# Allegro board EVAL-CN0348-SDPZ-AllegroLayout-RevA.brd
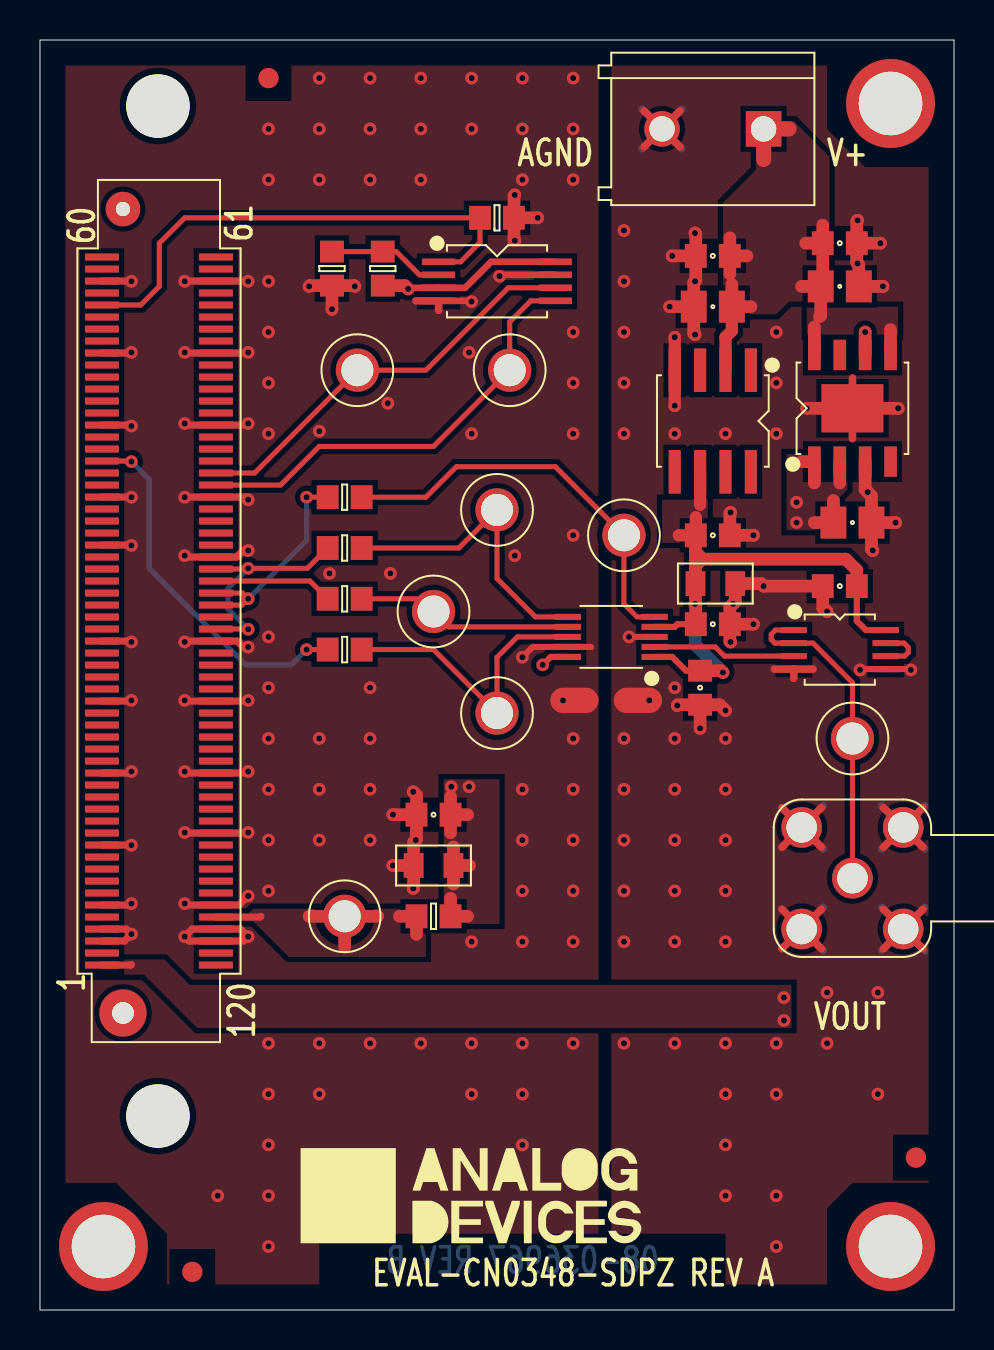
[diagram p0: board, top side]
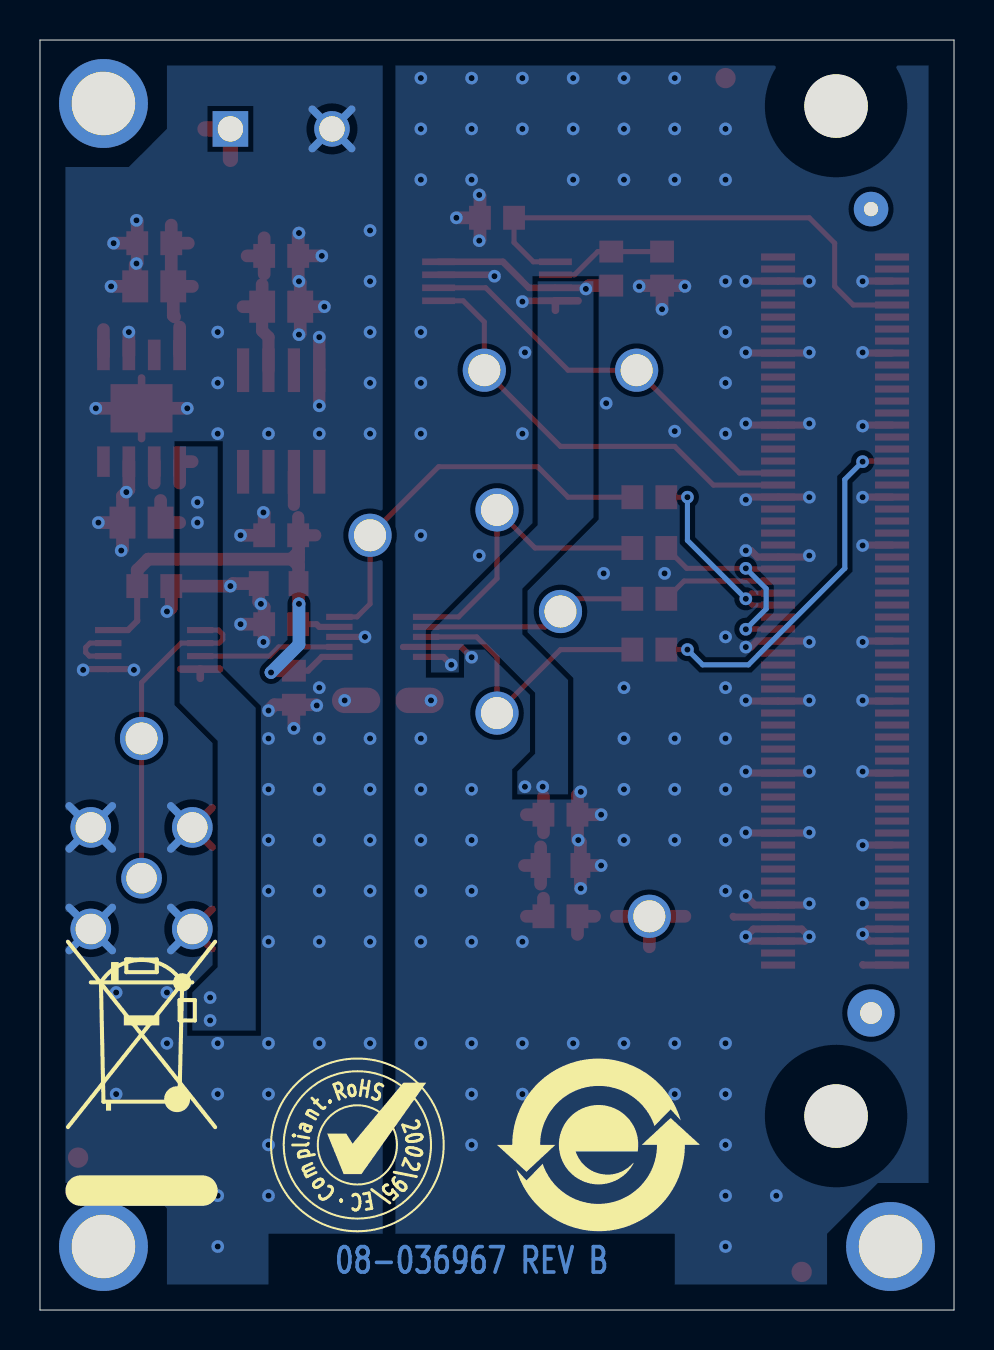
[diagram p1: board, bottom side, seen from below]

Outline 45.72 x 63.5 mm; copper layers: TOP, BOTTOM. Coordinates in mm from the lower left corner of the outline.
Outline path: 0,63.5 0,0 45.72,0 45.72,63.5 0,63.5

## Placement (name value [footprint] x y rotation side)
C1  0.1uF  [C0805]  40 51.18 0 top
C2  1UF  [C0603]  40 53.34 0 top
C3  1uF  [C0805]  40.64 39.37 0 top
C4  0.1uF  [C0805]  33.66 50.16 180 top
C5  1UF  [C0603]  33.66 52.7 180 top
C6  0.1uF  [C0603]  33.66 38.73 0 top
C7  0.1uF  [C0603]  33.66 34.29 180 top
C8  10uF  [C0805-2]  33.78 36.32 180 top
C9  0.1uF  [C0603]  33.02 31.11 270 top
C10  0.1uF  [C0603]  40 36.2 0 top
C12  10uF  [C0805-2]  19.69 22.23 180 top
C13  0.1uF  [C0603]  19.69 24.77 180 top
CS  BLK  [CNLOOPTP]  29.21 38.73 0 top
DIN  BLK  [CNLOOPTP]  19.69 34.92 0 top
J1  KRM2 02  [CNTERM_2P]  36.2 59.05 180 top
J2  FX8-120S-SV(21)  [CNHRSFX8-120S-SV_A]  5.95 34.95 90 top
J3  MACOM5164-5003-09  [CNMACOM5164-5003-09]  40.64 21.59 180 top
LDAC  BLK  [CNLOOPTP]  22.86 29.84 0 top
NOREF  -  []  -47.88 212.47 0 top
NOREF#2  -  [unnamed#2]  3.17 3.17 0 top
NOREF#3  -  []  -184.15 -215.9 0 top
NOREF#4  -  []  28.57 90.81 0 top
NOREF#5  -  []  0 0 0 top
NOREF#6  -  []  0 0 0 top
NOREF#7  -  []  182.25 261.87 0 top
NOREF#8  -  []  21.59 5.71 0 top
NOREF#9  -  []  11.43 61.59 0 top
NOREF#10  -  []  0 63.5 0 top
NOREF#11  -  []  -125.48 255.91 0 top
NOREF#12  -  []  -182.88 -214.63 0 top
NOREF#13  -  []  45.72 0 90 top
NOREF#14  -  [unnamed#2]  7.62 1.91 0 top
NOREF#15  -  [unnamed#2]  43.81 7.62 0 top
NOREF#16  -  []  11.43 61.59 0 top
NOREF#17  -  [unnamed#2]  42.55 3.17 0 top
NOREF#18  -  []  11.43 61.59 0 top
NOREF#19  -  []  0 63.5 0 top
NOREF#20  -  []  45.72 0 90 top
NOREF#21  -  []  -175.26 -205.49 0 top
NOREF#22  -  [unnamed#2]  42.55 60.32 0 top
NOREF#23  -  []  0 0 0 top
NOREF#24  -  [unnamed#2]  11.43 61.59 0 top
NOREF#25  -  []  45.72 63.5 0 top
NOREF#26  -  []  45.72 63.5 180 top
NOREF#27  -  []  0 63.5 270 top
NOREF#28  -  []  17.78 8.25 180 bottom
NOREF#29  -  []  29.84 8.25 180 bottom
NOREF#30  -  []  31.37 22.1 180 bottom
R1  33  [R0603]  15.24 40.64 0 top
R2  33  [R0603]  15.24 35.56 0 top
R3  33  [R0603]  15.24 38.1 0 top
R4  33  [R0603]  15.24 33.02 0 top
R5  100K  [R0603]  22.86 54.61 0 top
R6  0  [R0603]  17.14 52.07 90 top
R7  100K  [R0603]  14.61 52.07 270 top
R8  0  [R0603]  19.69 19.69 0 top
SCL  BLK  [CNLOOPTP]  15.88 46.99 0 top
SCLK  BLK  [CNLOOPTP]  22.86 40 0 top
SDA  BLK  [CNLOOPTP]  23.49 46.99 0 top
SNS1  SNS  [NCSNS50MIL]  27.3 30.48 0 top
U1  ADP7104ARDZ-5.0  [SO8NB-PAD3_1X2_41]  40.64 45.08 0 top
U2  ADR4550BRZ  [SO8]  33.66 44.45 180 top
U3  AD5541ABRMZ  [RM10]  28.57 33.66 90 top
U4  ADA4500-2AMRZ  [MSOP8]  40 33.02 270 top
U5  24LC32A-I/ST  [TSSOP8]  22.86 51.44 270 top
UNK3.3V  BLK  [CNLOOPTP]  15.24 19.69 0 top
VOUT  BLK  [CNLOOPTP]  40.64 28.57 0 top

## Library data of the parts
C1 C4 = CAP: Tolerance: 10; User Part Number: UPN; alternate symbols: (C0402H22_ALT,C0201-2,C0402_A); part number: CAP_SM-0.1UF,25V,10,E012855,C0805; tolerance: 10
C2 C5 = CAP: Tolerance: 10; User Part Number: UPN; alternate symbols: (C0402H22_ALT,C0201-2,C0402_A); part number: CAP_SM-1UF,25V,10,E006992,C0603; tolerance: 10
C3 = CAP: Tolerance: 10; User Part Number: UPN; alternate symbols: (C0402H22_ALT,C0201-2,C0402_A); part number: CAP_SM-1UF,16V,10,E011046,C0805; tolerance: 10
C6 C7 C9 C10 C13 = CAP: Tolerance: 10; User Part Number: UPN; alternate symbols: (C0402H22_ALT,C0201-2,C0402_A); part number: CAP_SM-0.1UF,16V,10,E011547,C0603; tolerance: 10
C8 C12 = CAP: Tolerance: 10; User Part Number: UPN; alternate symbols: (C0402H22_ALT,C0201-2,C0402_A); part number: CAP_SM-10UF,10V,10,E013940,C0805-2; tolerance: 10
CS DIN LDAC SCL SCLK SDA UNK3.3V VOUT = CNTP1P: User Part Number: UPN; alternate symbols: (CNBANANA_ALT); part number: CNTP1P_TH-BLK,E000948,CNLOOPTP
J1 = CN2P: User Part Number: UPN; part number: CN2P_TH-KRM2 02,E000796,CNTERM_2P
J2 = CN120P_V4: User Part Number: UPN; part number: CN120P_V4_SM-FX8-120S-SV(21),E016993,CNHRSFX8-120S-SV_A
J3 = CNBNC5P: User Part Number: UPN; part number: CNBNC5P_TH-MACOM5164-5003-09,E000920,CNMACOM5164-5003-09
R1-R4 = RES: Tolerance: 1; User Part Number: UPN; alternate symbols: (RRAD984L1500W75H520LD32;TO220H590_ALT;R0402_A;R0603_A); part number: RES_SM-33,1/4W,1,E019276,R0603; tolerance: 1
R5 R7 = RES: Tolerance: 1; User Part Number: UPN; alternate symbols: (RRAD984L1500W75H520LD32;TO220H590_ALT;R0402_A;R0603_A); part number: RES_SM-100K,1/10W,1,E010279,R0603; tolerance: 1
R6 R8 = RES: Tolerance: 1; User Part Number: UPN; alternate symbols: (RRAD984L1500W75H520LD32;TO220H590_ALT;R0402_A;R0603_A); part number: RES_SM-0,1/16W,1,E004207,R0603; tolerance: 1
SNS1 = NCSENSE: User Part Number: UPN; part number: NCSENSE_SM-SNS,E005619,NCSNS50MIL
U1 = ADP7104: User Part Number: UPN; part number: ADP7104_SM-ADP7104ARDZ-5.0,E016720,SO8NB-PAD3_1X2_41,N/A
U2 = ADR45XX: User Part Number: UPN; part number: ADR45XX_SM-ADR4550BRZ,E016255,SO8,N/A
U3 = AD5541A: User Part Number: UPN; part number: AD5541A_SM-AD5541ABRMZ,E015582,RM10,N/A
U4 = ADA4500_2: User Part Number: UPN; part number: ADA4500_2_SM-ADA4500-2AMRZ,E017613,MSOP8,N/A
U5 = IC24FC256: User Part Number: UPN; part number: IC24FC256_SM-24LC32A-I/ST,E014553,TSSOP8

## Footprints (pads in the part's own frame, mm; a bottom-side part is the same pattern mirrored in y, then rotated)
C0603
  rect 1.092x1.194 smd: 1(-0.851,0) 2(0.851,0)
C0805
  rect 1.295x1.6 smd: 1(-0.953,0) 2(0.953,0)
C0805-2
  rect 0.991x1.245 smd: 1(-0.996,0) 2(0.996,0)
CNHRSFX8-120S-SV_A
  round 3.302 hole 3.175 unplated: (-25.25,0.051) (25.25,0.051)
  round 2.362 hole 1.092 unplated: (-20.099,1.801)
  round 1.727 hole 0.711 unplated: (20.099,1.801)
  rect 0.356x1.702 smd: 1(-17.701,2.85) 2(-17.099,2.85) 3(-16.5,2.85) 4(-15.9,2.85) 5(-15.301,2.85) 6(-14.699,2.85) 7(-14.1,2.85) 8(-13.5,2.85) 9(-12.901,2.85) 10(-12.301,2.85) 11(-11.699,2.85) 12(-11.1,2.85) 13(-10.5,2.85) 14(-9.901,2.85) 15(-9.299,2.85) 16(-8.7,2.85) 17(-8.1,2.85) 18(-7.501,2.85) 19(-6.901,2.85) 20(-6.299,2.85) 21(-5.7,2.85) 22(-5.1,2.85) 23(-4.501,2.85) 24(-3.899,2.85) 25(-3.299,2.85) 26(-2.7,2.85) 27(-2.101,2.85) 28(-1.501,2.85) 29(-0.899,2.85) 30(-0.3,2.85) 31(0.3,2.85) 32(0.899,2.85) 33(1.501,2.85) 34(2.101,2.85) 35(2.7,2.85) 36(3.299,2.85) 37(3.899,2.85) 38(4.501,2.85) 39(5.1,2.85) 40(5.7,2.85) 41(6.299,2.85) 42(6.901,2.85) 43(7.501,2.85) 44(8.1,2.85) 45(8.7,2.85) 46(9.299,2.85) 47(9.901,2.85) 48(10.5,2.85) 49(11.1,2.85) 50(11.699,2.85) 51(12.301,2.85) 52(12.901,2.85) 53(13.5,2.85) 54(14.1,2.85) 55(14.699,2.85) 56(15.301,2.85) 57(15.9,2.85) 58(16.5,2.85) 59(17.099,2.85) 60(17.701,2.85) 61(17.701,-2.85) 62(17.099,-2.85) 63(16.5,-2.85) 64(15.9,-2.85) 65(15.301,-2.85) 66(14.699,-2.85) 67(14.1,-2.85) 68(13.5,-2.85) 69(12.901,-2.85) 70(12.301,-2.85) 71(11.699,-2.85) 72(11.1,-2.85) 73(10.5,-2.85) 74(9.901,-2.85) 75(9.299,-2.85) 76(8.7,-2.85) 77(8.1,-2.85) 78(7.501,-2.85) 79(6.901,-2.85) 80(6.299,-2.85) 81(5.7,-2.85) 82(5.1,-2.85) 83(4.501,-2.85) 84(3.899,-2.85) 85(3.299,-2.85) 86(2.7,-2.85) 87(2.101,-2.85) 88(1.501,-2.85) 89(0.899,-2.85) 90(0.3,-2.85) 91(-0.3,-2.85) 92(-0.899,-2.85) 93(-1.501,-2.85) 94(-2.101,-2.85) 95(-2.7,-2.85) 96(-3.299,-2.85) 97(-3.899,-2.85) 98(-4.501,-2.85) 99(-5.1,-2.85) 100(-5.7,-2.85) 101(-6.299,-2.85) 102(-6.901,-2.85) 103(-7.501,-2.85) 104(-8.1,-2.85) 105(-8.7,-2.85) 106(-9.299,-2.85) 107(-9.901,-2.85) 108(-10.5,-2.85) 109(-11.1,-2.85) 110(-11.699,-2.85) 111(-12.301,-2.85) 112(-12.901,-2.85) 113(-13.5,-2.85) 114(-14.1,-2.85) 115(-14.699,-2.85) 116(-15.301,-2.85) 117(-15.9,-2.85) 118(-16.5,-2.85) 119(-17.099,-2.85) 120(-17.701,-2.85)
CNLOOPTP
  round 2.159 hole 1.6: 1(0,0)
CNMACOM5164-5003-09
  round 2.032 hole 1.524: 1(0,0) 2(-2.54,2.54) 3(2.54,2.54) 4(2.54,-2.54) 5(-2.54,-2.54)
CNTERM_2P
  rect 1.778x1.778 hole 1.27: 1(0,0)
  round 1.778 hole 1.27: 2(5.08,0)
MSOP8
  rect 0.305x1.321 smd: 1(-0.975,-2.301) 2(-0.325,-2.301) 3(0.325,-2.301) 4(0.975,-2.301) 5(0.975,2.301) 6(0.325,2.301) 7(-0.325,2.301) 8(-0.975,2.301)
NCSNS50MIL
  round 0.127 smd: 1(0,0) 2(2.032,0)
R0603
  rect 1.092x1.194 smd: 1(-0.851,0) 2(0.851,0)
RM10
  rect 0.305x1.321 smd: 1(-1.001,-2.172) 2(-0.5,-2.172) 3(0,-2.172) 4(0.5,-2.172) 5(1.001,-2.172) 6(1.001,2.172) 7(0.5,2.172) 8(0,2.172) 9(-0.5,2.172) 10(-1.001,2.172)
SO8
  rect 0.61x2.184 smd: 1(-1.905,-2.54) 2(-0.635,-2.54) 3(0.635,-2.54) 4(1.905,-2.54) 5(1.905,2.54) 6(0.635,2.54) 7(-0.635,2.54) 8(-1.905,2.54)
SO8NB-PAD3_1X2_41
  rect 0.635x1.524 smd: 1(-1.905,-2.667) 2(-0.635,-2.667) 3(0.635,-2.667) 4(1.905,-2.667) 5(1.905,2.667) 6(0.635,2.667) 7(-0.635,2.667) 8(-1.905,2.667)
  rect 3.099x2.413 smd: PAD(0,0)
TSSOP8
  rect 0.33x1.651 smd: 1(-0.975,-2.921) 2(-0.325,-2.921) 3(0.325,-2.921) 4(0.975,-2.921) 5(0.975,2.921) 6(0.325,2.921) 7(-0.325,2.921) 8(-0.975,2.921)
unnamed#2
  round 4.445 hole 3.175 unplated: (0,0)

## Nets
3.3V: C12.1(N1) C13.1(N1) R6.1(N1) R8.2(N2) U3.10(VLOGIC) U5.3(A2) U5.8(VCC)
+5V: C6.1(N1) C7.2(N2) C8.2(N2) C9.1(N1) C10.2(N2) U2.6(VOUT) U3.1(VDD) U3.4(REF) U4.8(V+)
AGND: C1.2(N2) C2.2(N2) C3.2(N2) C4.2(N2) C5.2(N2) C6.2(N2) C7.1(N1) C8.1(N1) C9.2(N2) C10.1(N1) J1.2(N2) J3.2(SH1) J3.3(SH2) J3.4(SH3) J3.5(SH4) SNS1.2(N2) U1.3(GND1) U1.6(GND2) U1.PAD U2.4(GND) U3.3(AGND) U4.4(V-) U4.5(NINV)
DGND: C12.2(N2) C13.2(N2) J2.3(GND1) J2.4(GND2) J2.6(GND3) J2.11(GND4) J2.17(GND5) J2.23(GND6) J2.28(GND7) J2.36(GND8) J2.40(GND9) J2.46(GND10) J2.52(GND11) J2.58(GND12) J2.63(GND13) J2.69(GND14) J2.75(GND15) J2.81(GND16) J2.86(GND17) J2.93(GND18) J2.98(GND19) J2.104(GND20) J2.109(GND21) J2.115(GND22) J2.117(GND23) J2.118(GND24) R5.2(N2) R7.2(N2) SNS1.1(N1) U3.9(DGND) U5.4(VSS) U5.7(WP)
DAC_/LDAC: J2.43(GPIO0) R4.1(N1)
DAC_CS: J2.89(SPORT_TFS) J2.90(SPORT_RFS) R1.1(N1)
DAC_DIN: J2.88(SPORT_DT0) R2.1(N1)
DAC_SCLK: J2.87(SPORT_TSCLK) J2.92(SPORT_RSCLK) R3.1(N1)
SDP_+5V: C3.1(N1) J2.1(VIN) U1.1(VOUT) U1.2(SENSE)
UNNAMED_3_CN120PV4_I1_EEPROMA0: J2.56(EEPROM_A0) R5.1(N1) U5.1(A0)
UNNAMED_3_CN120PV4_I1_SCL0: J2.79(SCL_0) SCL.1(N1) U5.6(SCL)
UNNAMED_3_CN120PV4_I1_SDA0: J2.80(SDA_0) SDA.1(N1) U5.5(SDA)
UNNAMED_3_CN120PV4_I1_VIO: J2.116(VIO(+3.3V)) R8.1(N1) UNK3.3V.1
UNNAMED_3_IC24FC256_I4_A1: R6.2(N2) R7.1(N1) U5.2(A1)
UNNAMED_5_AD5541A_I1_CSN: CS.1(N1) R1.2(N2) U3.5(CS_N)
UNNAMED_5_AD5541A_I1_DIN: DIN.1(N1) R2.2(N2) U3.7(DIN)
UNNAMED_5_AD5541A_I1_LDACN: LDAC.1(N1) R4.2(N2) U3.8(LDAC_N)
UNNAMED_5_AD5541A_I1_SCLK: R3.2(N2) SCLK.1(N1) U3.6(SCLK)
UNNAMED_5_AD5541A_I1_VOUT: U3.2(VOUT) U4.3(NINV)
UNNAMED_5_ADA45002_I16_INV: U4.6(INV) U4.7(OUT)
VOUT: J3.1(CNTR) U4.1(OUT) U4.2(INV) VOUT.1(N1)
VPOS: C1.1(N1) C2.1(N1) C4.1(N1) C5.1(N1) J1.1(N1) U1.5(EN) U1.8(VIN) U2.2(VIN)

Pads without a net: J2 2 5 7 8 9 10 12 13 14 15 16 18 19 20 21 22 24 25 26 27 29 30 31 32 33 34 35 37 38 39 41 42 44 45 47 48 49 50 51 53 54 55 57 59 60 61 62 64 65 66 67 68 70 71 72 73 74 76 77 78 82 83 84 85 91 94 95 96 97 99 100 101 102 103 105 106 107 108 110 111 112 113 114 119 120; U1 4 7; U2 1 3 5 7 8

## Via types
v1: diameter 0.635, hole 0.305, TOP to BOTTOM, 208 vias

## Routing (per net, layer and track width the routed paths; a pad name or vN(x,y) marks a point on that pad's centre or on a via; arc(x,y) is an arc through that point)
3.3V: length 17.8
  TOP w0.305: v1(25.15,32.26) 25.54,32.65 U3.10
  TOP w0.33: U5.8 22.57,52.41 21.26,51.11 U5.3 18.47,51.11 v1(18.41,51.05)
  TOP w0.635: C13.1 20.54,25.67 ; C13.1 21.39,24.77 ; C13.1 20.54,23.86 ; C12.1 20.68,23.15 ; C12.1 21.48,22.23 ; C12.1 20.68,21.3 ; v1(18.41,51.05) 18.25,51.22 R6.1 ; 20.54,20.59 R8.2 21.39,19.69
  vias: v1(20.57,26.16) v1(21.46,26.16)
+5V: length 31.2
  TOP w0.305: U4.8 41.32,34 40.86,34.46 C10.2 ; U3.1 31.62,32.65 32.31,31.97 C9.1 ; C7.2 31.88,34.29 31.75,34.16 U3.4
  TOP w0.61: U2.6 33.02,40.26 ; 32.8,39.64 C6.1 31.95,38.73
  TOP w0.635: 32.79,37.9 32.79,38.72 C6.1 ; 32.79,37.9 33.15,37.54 ; 32.79,37.9 32.79,37.59 ; 32.79,37.21 C8.2 32.79,35.33 v1(32.77,35.31) 32.8,35.27 C7.2 ; 32.79,37.21 32.79,37.59 ; 32.79,37.21 33.12,37.54 ; 33.12,37.54 33.15,37.54 ; 33.12,37.54 32.84,37.54 32.79,37.59 ; 33.15,37.54 40.31,37.54 40.86,37 C10.2 ; C9.1 34.07,31.97 v1(34.16,31.88)
  BOTTOM w0.635: v1(34.16,31.88) 32.77,33.27 v1(32.77,35.31)
AGND: length 107.1
  TOP w0.305: v1(41.02,32) 41.06,32.04 U4.5 43.52,32.04 v1(43.56,32) ; U3.3 v1(29.46,33.66)
  TOP w0.381: SNS1.2 29.34,30.85 ; SNS1.2 29.34,30.11 ; SNS1.2 28.97,30.48 ; U4.4 38.67,32.04 ; U4.4 36.74,32.04 ; U4.4 37.7,31.58 ; 42.19,20.04 J3.2 ; J3.2 42.19,18.06 ; J3.2 44.17,20.04 ; J3.2 44.17,18.06 ; J3.4 39.09,25.12 ; J3.4 37.11,23.14 ; J3.4 37.11,25.12 ; J3.4 39.09,23.14 ; 30.22,58.16 31.11,59.05 ; 31.11,59.05 32.01,59.95 ; 31.11,59.05 32.01,58.16 ; 31.11,59.05 30.22,59.95 ; 40.64,43.57 U1.PAD 40.64,46.6 ; 37.11,20.04 J3.3 ; J3.3 39.09,18.06 ; J3.3 39.09,20.04 ; J3.3 37.11,18.06 ; J3.5 44.17,25.12 ; J3.5 42.19,23.14 ; J3.5 42.19,25.12 ; J3.5 44.17,23.14
  TOP w0.61: v1(31.75,48.64) U2.4 v1(31.75,45.21)
  TOP w0.635: v1(32.77,48.77) 32.7,48.83 C4.2 ; 41.27,47.75 v1(41.27,48.89) ; C9.2 31.92,30.26 v1(31.88,30.23) ; C9.2 34,30.26 v1(34.29,29.97) ; C9.2 v1(33.02,29.08) ; C4.2 v1(31.5,50.16) ; C4.2 32.7,51.37 v1(32.77,51.44) 32.8,51.47 C5.2 ; C7.1 34.51,33.44 v1(34.54,33.4) ; C7.1 34.51,35.14 v1(34.67,35.31) 34.78,35.41 C8.1 36.07,36.32 v1(36.2,36.2) C10.1 39.15,35.09 v1(39.37,34.92) ; C7.1 v1(35.69,34.29) ; v1(32.77,53.85) 32.8,53.81 C5.2 ; v1(41.66,37.97) 41.59,38.04 C3.2 ; C5.2 v1(31.62,52.7) ; v1(40.89,54.48) 40.86,54.44 C2.2 ; C3.2 v1(42.8,39.37) ; C3.2 41.59,40.7 v1(41.4,40.89) 41.27,41.02 41.27,42.42 ; v1(35.69,38.73) C6.2 34.51,39.84 v1(34.54,39.88) ; C2.2 v1(42.04,53.34) ; C2.2 40.86,52.36 v1(40.89,52.32) 40.96,52.26 C1.2 v1(42.16,51.18) ; v1(42.93,45.08) U1.PAD v1(38.35,45.08)
  TOP w1.27: SNS1.2 v1(30.48,30.48)
  BOTTOM w0.381: 42.1,23.05 J3.5 ; J3.5 44.26,23.05 ; J3.5 42.1,25.21 ; J3.5 44.26,25.21 ; 39.18,17.97 J3.3 39.18,20.13 ; 31.11,59.05 32.1,58.07 ; 31.11,59.05 30.13,60.04 ; 31.11,59.05 32.1,60.04 ; 31.11,59.05 30.13,58.07 ; J3.2 44.26,17.97 ; J3.2 42.1,20.13 ; J3.2 42.1,17.97 ; J3.2 44.26,20.13 ; 39.18,25.21 J3.4 39.18,23.05
  vias: v1(29.21,53.98) v1(29.21,51.44) v1(29.21,48.89) v1(29.21,46.35) v1(29.21,43.81) v1(29.21,28.57) v1(29.21,26.03) v1(29.21,23.49) v1(29.21,20.95) v1(29.21,18.41) v1(29.21,13.34) v1(31.75,43.81) v1(31.75,31.11) v1(31.75,28.57) v1(31.75,26.03) v1(31.75,23.49) v1(31.75,20.95) v1(31.75,18.41) v1(31.75,13.34) v1(34.29,43.81) v1(34.29,28.57) v1(34.29,26.03) v1(34.29,23.49) v1(34.29,20.95) v1(34.29,18.41) v1(34.29,13.34) v1(34.29,10.8) v1(34.29,8.25) v1(34.29,5.71) v1(36.83,48.89) v1(36.83,46.35) v1(36.83,43.81) v1(36.83,13.34) v1(36.83,10.8) v1(36.83,5.71) v1(36.83,3.17) v1(39.37,15.88) v1(39.37,13.34) v1(41.91,15.88) v1(41.91,10.8)
DGND: length 83.6
  TOP w0.305: 27.56,33.15 27.55,33.15 U3.9 24.65,33.15 v1(24.13,32.64)
  TOP w0.33: U5.4 21.55,50.46 v1(21.59,50.42) ; v1(22.99,51.69) 23.06,51.76 U5.7
  TOP w0.356: v1(4.57,47.88) 4.54,47.85 J2.52 ; v1(10.41,26.92) 10.34,26.85 J2.104 7.32,26.85 v1(7.24,26.92) ; v1(4.57,51.44) 4.56,51.45 J2.58 ; v1(4.57,44.2) 4.52,44.25 J2.46 ; J2.23 4.54,30.45 v1(4.57,30.48) ; v1(10.41,37.97) 10.16,37.97 9.83,37.65 J2.86 7.31,37.65 v1(7.24,37.72) ; J2.11 4.56,23.25 v1(4.57,23.24) ; J2.28 4.53,33.45 v1(4.57,33.4) ; v1(4.57,20.32) 4.5,20.25 J2.6 ; v1(7.24,40.64) 7.25,40.65 J2.81 10.28,40.65 v1(10.41,40.51) ; v1(7.24,30.48) 7.27,30.45 J2.98 10.38,30.45 v1(10.41,30.48) ; v1(10.41,44.32) 10.34,44.25 J2.75 7.32,44.25 v1(7.24,44.32) ; J2.17 4.5,26.85 v1(4.57,26.92) ; v1(7.24,23.88) 7.27,23.85 J2.109 10.39,23.85 v1(10.41,23.88) ; J2.40 4.56,40.65 v1(4.57,40.64) ; v1(4.57,38.23) 4.55,38.25 J2.36 ; v1(10.41,47.88) 10.38,47.85 J2.69 7.27,47.85 v1(7.24,47.88) ; v1(10.41,20.7) 9.96,20.25 J2.115 7.31,20.25 v1(7.24,20.32) ; J2.4 4.32,19.05 v1(4.57,18.8) 4.22,18.45 J2.3 ; v1(7.24,51.44) 7.25,51.45 J2.63 10.4,51.45 v1(10.41,51.44) ; v1(7.24,33.4) 7.28,33.45 J2.93 9.86,33.45 10.16,33.15 v1(10.41,33.15) ; J2.118 10.19,18.45 v1(10.41,18.67) 10.04,19.05 J2.117 7.62,19.05 v1(7.24,18.67) 7.46,18.45 J2.118
  TOP w0.381: 18.81,50.46 U5.4 19.94,49.99 ; SNS1.1 27.68,30.48 ; SNS1.1 27.3,30.11 ; SNS1.1 27.3,30.85
  TOP w0.635: R5.2 v1(24.89,54.61) ; R5.2 23.71,53.51 v1(23.75,53.47) ; R5.2 23.71,55.71 v1(23.75,55.75) ; R7.2 v1(14.61,50.04) ; R7.2 13.5,51.22 v1(13.46,51.18) ; R7.2 15.71,51.22 v1(15.75,51.18) ; v1(18.67,25.91) 18.83,25.74 C13.2 ; C12.2 v1(17.65,22.23) ; C12.2 18.69,21.1 v1(18.67,21.08) ; C12.2 18.69,23.39 v1(18.8,23.49) 18.83,23.53 C13.2 ; C13.2 v1(17.65,24.77)
  TOP w1.27: SNS1.1 v1(26.16,30.48)
  vias: v1(8.89,5.71) v1(11.43,59.05) v1(11.43,56.52) v1(11.43,51.44) v1(11.43,48.89) v1(11.43,46.35) v1(11.43,43.81) v1(11.43,33.66) v1(11.43,31.11) v1(11.43,28.57) v1(11.43,26.03) v1(11.43,23.49) v1(11.43,20.95) v1(11.43,13.34) v1(11.43,10.8) v1(11.43,8.25) v1(11.43,5.71) v1(11.43,3.17) v1(13.97,61.59) v1(13.97,59.05) v1(13.97,56.52) v1(13.97,43.94) v1(13.97,28.57) v1(13.97,26.03) v1(13.97,23.49) v1(13.97,13.34) v1(13.97,10.8) v1(14.48,36.83) v1(16.51,61.59) v1(16.51,59.05) v1(16.51,56.52) v1(16.51,31.11) v1(16.51,28.57) v1(16.51,26.03) v1(16.51,23.49) v1(16.51,13.34) v1(17.4,45.34) v1(17.53,36.83) v1(19.05,61.59) v1(19.05,59.05) v1(19.05,56.52) v1(19.05,13.34) v1(21.46,47.88) v1(21.59,61.59) v1(21.59,59.05) v1(21.59,43.81) v1(21.59,18.41) v1(21.59,13.34) v1(21.59,10.8) v1(23.75,37.72) v1(24.13,61.59) v1(24.13,59.05) v1(24.13,56.52) v1(24.13,26.03) v1(24.13,23.49) v1(24.13,20.95) v1(24.13,18.41) v1(24.13,13.34) v1(24.13,10.8) v1(24.13,8.25) v1(26.67,61.59) v1(26.67,59.05) v1(26.67,56.52) v1(26.67,48.89) v1(26.67,46.35) v1(26.67,43.81) v1(26.67,38.73) v1(26.67,28.57) v1(26.67,26.03) v1(26.67,23.49) v1(26.67,20.95) v1(26.67,18.41) v1(26.67,13.34)
DAC_/LDAC: length 18.4
  TOP w0.254: R4.1 v1(13.33,33.02) ; J2.43 4.54,42.45 v1(4.57,42.42)
  BOTTOM w0.254: v1(4.57,42.42) 5.46,41.53 5.46,37.08 10.29,32.26 12.57,32.26 v1(13.33,33.02)
DAC_CS: length 10.8
  TOP w0.254: J2.90 10.1,35.25 v1(10.41,35.56) 10.13,35.85 J2.89 ; R1.1 v1(13.33,40.64)
  BOTTOM w0.254: v1(10.41,35.56) 13.33,38.48 v1(13.33,40.64)
DAC_DIN: length 6
  TOP w0.254: R2.1 13.5,36.45 J2.88
DAC_SCLK: length 11.5
  TOP w0.254: v1(10.41,34.04) 10.4,34.05 J2.92 ; R3.1 13.37,37.08 v1(10.41,37.08) 10.38,37.05 J2.87
  BOTTOM w0.254: v1(10.41,34.04) 9.4,35.05 9.4,36.07 v1(10.41,37.08)
SDP_+5V: length 6.3
  TOP w0.356: 4.57,17.27 4.55,17.25 J2.1
  TOP w0.635: 38.11,42.42 U1.1 38.73,41.35 ; 39.69,40.48 C3.1 38.73,39.37 ; U1.2 40,41.35
  vias: v1(37.21,15.62) v1(37.21,14.48) v1(37.85,40.39) v1(37.85,39.37)
UNNAMED_3_CN120PV4_I1_EEPROMA0: length 25.7
  TOP w0.254: U5.1 21.04,52.41 22.01,53.38 R5.1 7.24,54.61 5.97,53.34 5.97,51.18 5.04,50.25 J2.56
UNNAMED_3_CN120PV4_I1_SCL0: length 20.8
  TOP w0.254: J2.79 10.73,41.85 SCL.1 19.3,46.99 23.42,51.11 U5.6
UNNAMED_3_CN120PV4_I1_SDA0: length 22.2
  TOP w0.254: U5.5 24.55,50.46 23.49,49.4 SDA.1 19.69,43.18 13.97,43.18 12.04,41.25 J2.80
UNNAMED_3_CN120PV4_I1_VIO: length 9
  TOP w0.356: J2.116 11.01,19.65 11.05,19.69
  TOP w0.635: 18.83,18.78 R8.1 17.98,19.69 ; UNK3.3V.1 13.46,19.69 ; UNK3.3V.1 15.24,18.16 ; UNK3.3V.1 16.89,19.69
UNNAMED_3_IC24FC256_I4_A1: length 5.8
  TOP w0.254: U5.2 18.98,51.76 17.82,52.92 R6.2 R7.1
UNNAMED_5_AD5541A_I1_CSN: length 20.4
  TOP w0.254: U3.5 29.86,34.66 29.21,35.31 CS.1 25.78,42.16 20.83,42.16 19.3,40.64 R1.2
UNNAMED_5_AD5541A_I1_DIN: length 10.9
  TOP w0.254: U3.7 20.45,34.16 DIN.1 19.05,35.56 R2.2
UNNAMED_5_AD5541A_I1_LDACN: length 14.8
  TOP w0.254: R4.2 19.69,33.02 LDAC.1 22.86,32.64 23.88,33.66 U3.8
UNNAMED_5_AD5541A_I1_SCLK: length 15.3
  TOP w0.254: U3.6 24.78,34.66 22.86,36.58 SCLK.1 20.95,38.1 R3.2
UNNAMED_5_AD5541A_I1_VOUT: length 7.1
  TOP w0.254: U3.2 33.77,33.15 34.23,32.69 U4.3
UNNAMED_5_ADA45002_I16_INV: length 2.7
  TOP w0.254: U4.7 43.22,33.35 43.43,33.13 43.43,32.88 43.25,32.69 U4.6
VOUT: length 16.2
  TOP w0.254: U4.1 36.79,34 36.58,33.78 36.58,33.53 36.76,33.35 U4.2 38.66,33.35 40.64,31.37 VOUT.1 J3.1
VPOS: length 20
  TOP w0.61: C4.1 34.61,48.96 34.29,48.64 U2.2
  TOP w0.635: C5.1 34.51,51.8 ; C5.1 35.36,52.7 ; C5.1 34.51,53.61 ; U1.8 38.73,49.15 ; C2.1 38.3,53.34 ; C2.1 39.15,54.24 ; C2.1 39.15,51.28 C1.1 ; C1.1 39.05,49.72 38.99,49.66 ; C1.1 38.1,51.18 ; U1.5 42.55,49.02 ; 34.61,51.27 C4.1 35.56,50.16
  TOP w0.762: 37.47,59.05 J1.1 36.2,57.53

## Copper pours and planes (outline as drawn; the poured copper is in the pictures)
3.3V on TOP: 20.19,19.3 20.19,26.54 22.99,26.54 22.99,19.3
3.3V on BOTTOM: 21.84,25.78 21.84,26.92 20.95,27.81 20.95,30.86 23.37,33.27 24.51,33.27 24.77,33.02 24.77,31.88 26.16,31.88 26.16,33.91 20.83,39.24 20.83,51.44 18.03,51.44 18.03,39.62 21.59,36.07 21.59,33.78 19.3,31.5 19.3,25.78
+5V on TOP: 31.11,38.35 31.11,40.51 32.64,40.51 32.64,41.27 33.4,41.27 33.4,38.35
AGND on TOP: 34.29,1.27 34.29,3.81 28.57,3.81 28.57,62.23 39.37,62.23 39.37,59.05 41.27,57.15 44.45,57.15 44.45,8.76 42.67,8.76 42.67,6.48 44.45,6.48 44.45,6.35 40.64,6.35 39.37,5.08 39.37,1.27 ; 5 cut-outs
AGND on BOTTOM: 34.29,1.27 34.29,3.81 28.57,3.81 28.57,62.23 39.37,62.23 39.37,59.05 41.27,57.15 44.45,57.15 44.45,6.35 40.64,6.35 39.37,5.08 39.37,1.27
DGND on TOP: 6.35,1.27 6.35,3.81 3.81,6.35 1.27,6.35 1.27,62.23 10.29,62.23 10.29,60.45 12.57,60.45 12.57,62.23 27.94,62.23 27.94,3.81 13.97,3.81 13.97,1.27 8.76,1.27 8.76,3.05 6.48,3.05 6.48,1.27 ; 1 cut-out
DGND on BOTTOM: 6.35,1.27 6.35,3.81 3.81,6.35 1.27,6.35 1.27,62.23 27.94,62.23 27.94,3.81 13.97,3.81 13.97,1.27
SDP_+5V on TOP: 37.34,38.99 37.34,42.8 38.23,42.8 38.23,41.4 40.39,41.4 40.39,41.02 40,40.64 40,38.99
SDP_+5V on TOP: 2.29,17.53 6.22,17.53 7.49,16.26 37.59,16.26 37.59,14.1 7.87,14.1 5.21,16.76 2.29,16.76
SDP_+5V on BOTTOM: 36.83,43.18 38.73,43.18 38.73,30.35 36.83,28.45 36.83,17.14 38.1,15.88 38.1,13.97 34.92,13.97 34.92,30.1 36.83,32
UNNAMED_3_CN120PV4_I1_VIO on TOP: 12.45,17.65 10.67,19.43 10.03,19.43 10.03,19.81 10.41,19.81 10.67,20.07 13.81,20.07 15.24,18.2 16.67,20.07 19.3,20.07 19.3,17.65
VPOS on TOP: 34.16,49.78 34.16,55.37 35.81,57.02 35.81,59.44 37.72,59.44 39.5,57.66 39.5,50.42 37.47,50.42 36.83,49.78
VPOS on TOP: 38.35,48.77 38.35,50.16 42.93,50.16 42.93,48.77

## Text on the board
BOTTOM: 08-036967 REV B
Ref Des/Silkscreen Top: AGND | EVAL-CN0348-SDPZ REV A | V+ | VOUT
DIMENSION: (REF) | NOTES: | 1. THE BOARD SIZE MAY VARY TO COMPENSATE THE COMPONENTS DENSITY OF THE CIRCUIT. | 2. THE BOARD MAY EXTEND TO THE RIGHT AND LOWER PORTION IF THERE IS A NEED TO CHANGE THE BOARD SIZE. | 3. J1 CONNECTOR LOCATION IS FIXED WITH REFERENCE TO THE DISTANCE ON BOARD EDGE ON THE UPPER LEFT PORTION.
PAGE_OUTLINE: V. WONG | OCT13 | NOV12 | N/A | B | AS PER ECR-043950 | EVALUATION BOARD
User.7: ROHS COMPLIANCE NOTE: | 100 MICRO INCHES NICKEL/ | 3-5 MICRO INCHES GOLD | HOMOGENOUS MATERIALS IN THIS BOARD SHALL BE COMPLIANT | THE EU RoHS DIRECTIVE 2002/95/EC
User.25: FIGURE | SIZE | 12.0 | 50.0 | 60.0 | 63.0 | 28.0 | 43.0 | 125.0 | DRILL CHART: TOP to BOTTOM | ALL UNITS ARE IN MILS | TOLERANCE | +3.0/-3.0 | +2.0/-2.0 | PLATED | NON-PLATED | QTY | 208 | 2 | 5 | 8 | 1
